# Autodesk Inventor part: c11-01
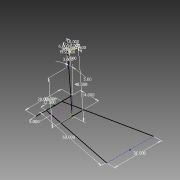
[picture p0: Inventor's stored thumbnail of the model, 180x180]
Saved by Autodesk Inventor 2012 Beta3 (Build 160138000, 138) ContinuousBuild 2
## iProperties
Created: 2010-12
Part Number: c11-01
Material: Default
Document SubType Name: Modeling
Designer: Beta-8540w
Density: 1 g/cm^3
Author: Beta-8540w
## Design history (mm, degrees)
sketch "Sketch1"
  geometry: L1 (355.6, 0)-(-355.6, 0); L2 (152.4, 0)-(457.2, 1493.209); L3 (-152.4, 0)-(-457.2, 1493.209); L4 (224.987, 355.6)-(-224.987, 355.6); L5 (457.2, 1493.209)-(-457.2, 1493.209); L6 (-178.324, 127)-(178.324, 127); 4 further points
  constraints: 12 end point, 6 point on line, 3 midpoint, 3 parallel, 2 vertical alignment, 1 coincident, 1 equal length, 1 horizontal
  dimensions: "d0" = 711.2 distance of L1.start L1.end; "d1" = 1524 distance of L2.start L2.end; "d2" = 304.8 distance of L3.start L2.start; "d3" = 355.6 distance between parallel lines of L1 L4; "d4" = 914.4 distance of L2.end L3.end; "d8" = 127 distance between parallel lines of L6 L1
sketch "Sketch2"
  geometry: L1 (355.6, 0)-(355.6, 346.923); L2 (355.6, 0)-(249.34, 1214.561); L3 (249.34, 1214.561)-(502.373, 1236.698); L4 (303.898, 1028.106)-(300.387, 1068.232); L5 (306.233, 1086.772)-(385.066, 1180.722); L6 (402.31, 1189.698)-(442.435, 1193.209); A1 r 25.4 centre (325.691, 1070.446) between (306.233, 1086.772) and (300.387, 1068.232); A2 r 25.4 centre (404.523, 1164.395) between (402.31, 1189.698) and (385.066, 1180.722); 3 further points
  constraints: 12 end point, 4 point on circle, 4 point on line, 4 tangent, 2 centre point, 2 parallel, 1 equal radius, 1 perpendicular, 1 vertical
  dimensions: "d5" = 1219.2 distance of L1.start L2.end; "d6" = 5 deg angle of L2 L1; "d11" = 254 distance of L2.end L3.end; "d12" = 50.8 distance of L4.start point (299.47, 1078.713) (= d13); "d13" = 50.8 distance of point (391.829, 1188.781) L6.end; "d14" = 25.4 radius of A1; "d15" = 45 deg angle of L5 L4; "d16" = 152.4 distance from line of L6 L4.start; "d17" = 38.1 distance between parallel lines of L3 L6; "d18" = 38.1 distance between parallel lines of L2 L4
workplane "Work Plane1"
sketch "Sketch3"
  geometry: L1 (224.987, 0)-(224.987, 1219.2) reference; L2 (186.887, 812.8)-(263.087, 812.8); 2 further points
  constraints: 2 end point, 1 midpoint, 1 perpendicular, 1 point on line
  dimensions: "d9" = 76.2 distance of L2.start L2.end; "d10" = 812.8 distance from line of L1.start L2
other parameters: "d16" = 152.4
